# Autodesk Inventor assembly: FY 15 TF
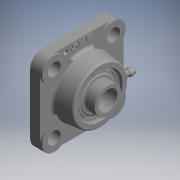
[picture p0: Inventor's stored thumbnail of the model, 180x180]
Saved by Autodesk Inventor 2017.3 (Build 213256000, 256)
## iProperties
Category: PARTsolutions
Company: SKF
Part Number: FY 15 TF
Catalog Web Link: www.cadenas.de
Description: AYF_001HC_HH_HY-Y-bearing square flanged units
Vendor: SKF
Document SubType Name: Assembly
Designer: partserver
Manufacturer: SKF
Mass: 370 g
Surface Area: 342.54 cm^2
Volume: 53.3408 cm^3
Density: 6.93652 g/cm^3
Title: FY 15 TF
Author: Cadenas PARTsolutions
Comments: Y-bearing square flanged units
PSOL_IDENT_0: {$CADENAS_DATA\23d-libs\skf\bearings_units_and_housings\bearing_units\ball_bearing_units\y-units\ayf
PSOL_IDENT_1: _001hc_hh_hy.prj},187 {VTYP=3D},{STYP=ASSTAB},{NB=FY 15 TF},{LINA=FY 15 TF},{NN=AYF_001HC_HH_HY},{DA
PSOL_IDENT_2: TE=20.08.2020 12:22:38},{GEOMDATE=20.08.2020 12:22:32},{VERSION=},{LINEID=58220},{WBVAR=COVER},{WBNU
PSOL_IDENT_3: MERIC=}  {NB=FY 15 TF},{LINA=FY 15 TF},{KT=DUMMY},{DESIGNATION=FY 15 TF},{HOUSING=FY 503 M},{BEARING=
PSOL_IDENT_4: YAR 203/15-2F},{COVER=},{DD=15},{DDX=},{DDALG=15.000},{DD1=24.200},{DD2=MIN},{DD3=},{AALG=26.000},{A=
PSOL_IDENT_5: 26},{AX=},{AXX=},{A1ALG=11.000},{A1=11},{A1X=},{A1XX=},{A3ALG=3.200},{A3=3.2},{A3X=},{A5ALG=0.000},{
PSOL_IDENT_6: A5=},{A5X=},{A5XX=},{B=27.400},{B1=MIN},{B1X=},{B4ALG=4.000},{B4=4},{B4X=},{DAAALG=55.600},{DAA=55.6
PSOL_IDENT_7: },{DAAX=},{DB=MIN},{DB1=50.000},{DB1X=},{DB2=53.000},{DB2X=},{HA=},{J=54.000},{JX=},{JXX=},{L=76.000
PSOL_IDENT_8: },{LX=},{LXX=},{N=11.500},{NX=},{NXX=},{SS1=15.900},{SS1X=},{T=32.900},{TX=},{DN=6.500},{SWN=7},{GN=
PSOL_IDENT_9: 1/4-28 SAE-LT},{RG=1/4-28 UNF},{RGX=},{R1=19},{R1X=},{J6=66},{J7=14.500},{N4=4},{D=40.000},{C=12.000
PSOL_IDENT_10: },{R12=0.300},{DW=6.747},{B3=MIN},{PITCH=28.500},{LOAD1=9.560},{LOAD2=4.750},{LOAD3=0.200},{SPEED1=9
PSOL_IDENT_11: 500},{II=1},{Z=8},{MASS=0.370},{MASSX=},{G2=M6x0.75},{HKSGS=3},{RTTGS=4},{ALPHA=},{GALG=10.000},{G=1
PSOL_IDENT_12: 0},{GX=},{GXX=},{GINALG=0.375},{GIN=0.375000002475},{GINX=},{GINXX=},{EC=},{BS=},{SLEEVE=},{POPULAR=
PSOL_IDENT_13: },{D1=MIN},{K=},{CC1=},{BRGTYP=BBY_006},{COVERALG=  '', 'No end cover' },{SUPPRESSED=unsuppressed},{
PSOL_IDENT_14: TC=FY 15 TF},{PPATH=y-bearing_square_flanged_units_parts/ayf_001hc_hh_hy_asmtpl.prj}
NB: FY 15 TF
NN: AYF_001HC_HH_HY
NT: Y-bearing square flanged units
NBSYN: $TC.
LINA: FY 15 TF
CATALOG: SKF
DESIGNATION: FY 15 TF
HOUSING: FY 503 M
BEARING: YAR 203/15-2F
COVER: No end cover
DDALG: 15
J: 54
L: 76
T: 32.9
LOAD1: 9.56
LOAD2: 4.75
SPEED1: 9500
SUPPLIER: SKF
ARTICLENO: FY 15 TF
BOMINFO: FY 15 TF
CREATOR: CADENAS GmbH
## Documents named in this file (6)
- e:\temp\worker_99\temp\exporttempdir_4692_6_LMKB5\format_0\FY 15 TF.iam
- e:\temp\worker_99\temp\exporttempdir_4692_6_LMKB5\format_0\FY 17 TF0_375000002475-dummy.ipt
- e:\temp\worker_99\temp\exporttempdir_4692_6_LMKB5\format_0\FY 503 M-housing.ipt
- e:\temp\worker_99\temp\exporttempdir_4692_6_LMKB5\format_0\1_4-28 SAE-LT.ipt
- e:\temp\worker_99\temp\exporttempdir_4692_6_LMKB5\format_0\YAR 203-2F-24_210300220312 -bearing.ipt
- e:\temp\worker_99\temp\exporttempdir_4692_6_LMKB5\format_0\17-40-27_4-12-ybrg1-43-6_747-28_5.ipt
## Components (12 placed, 5 different names)
1. FY 17 TF0_375000002475-dummy:1 — brg_XY@1 <-> housing_XY@2, brg_Z@1 <-> housing_Z@2, brg_YZ@1 <-> housing_YZ@2
2. FY 503 M-housing:1 — brg_XY@1 <-> housing_XY@2, brg_Z@1 <-> housing_Z@2, brg_YZ@1 <-> housing_YZ@2, gn_XY@2 <-> gn_XY@3, gn_Z@2 <-> gn_Z@3, gn_YZ@2 <-> gn_YZ@3, housing_XY@2 <-> brg3_XY@4, housing_Z@2 <-> brg3_Z@4, housing_YZ@2 <-> brg3_YZ@4
3. 1_4-28 SAE-LT:1 — gn_XY@2 <-> gn_XY@3, gn_Z@2 <-> gn_Z@3, gn_YZ@2 <-> gn_YZ@3
4. YAR 203-2F-24_210300220312 -bearing:1 — housing_XY@2 <-> brg3_XY@4, housing_Z@2 <-> brg3_Z@4, housing_YZ@2 <-> brg3_YZ@4, ball_1_XY@4 <-> ball_XY@5, ball_1_Z@4 <-> ball_Z@5, ball_1_YZ@4 <-> ball_YZ@5, ball_2_XY@4 <-> ball_XY@6, ball_2_Z@4 <-> ball_Z@6, ball_2_YZ@4 <-> ball_YZ@6, ball_3_XY@4 <-> ball_XY@7, ball_3_Z@4 <-> ball_Z@7, ball_3_YZ@4 <-> ball_YZ@7, ball_4_XY@4 <-> ball_XY@8, ball_4_Z@4 <-> ball_Z@8, ball_4_YZ@4 <-> ball_YZ@8, ball_5_XY@4 <-> ball_XY@9, ball_5_Z@4 <-> ball_Z@9, ball_5_YZ@4 <-> ball_YZ@9, ball_6_XY@4 <-> ball_XY@10, ball_6_Z@4 <-> ball_Z@10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
5. 17-40-27_4-12-ybrg1-43-6_747-28_5:1 — ball_1_XY@4 <-> ball_XY@5, ball_1_Z@4 <-> ball_Z@5, ball_1_YZ@4 <-> ball_YZ@5
6. 17-40-27_4-12-ybrg1-43-6_747-28_5:2 — ball_2_XY@4 <-> ball_XY@6, ball_2_Z@4 <-> ball_Z@6, ball_2_YZ@4 <-> ball_YZ@6
7. 17-40-27_4-12-ybrg1-43-6_747-28_5:3 — ball_3_XY@4 <-> ball_XY@7, ball_3_Z@4 <-> ball_Z@7, ball_3_YZ@4 <-> ball_YZ@7
8. 17-40-27_4-12-ybrg1-43-6_747-28_5:4 — ball_4_XY@4 <-> ball_XY@8, ball_4_Z@4 <-> ball_Z@8, ball_4_YZ@4 <-> ball_YZ@8
9. 17-40-27_4-12-ybrg1-43-6_747-28_5:5 — ball_5_XY@4 <-> ball_XY@9, ball_5_Z@4 <-> ball_Z@9, ball_5_YZ@4 <-> ball_YZ@9
10. 17-40-27_4-12-ybrg1-43-6_747-28_5:6 — ball_6_XY@4 <-> ball_XY@10, ball_6_Z@4 <-> ball_Z@10, ball_6_YZ@4 <-> ball_YZ@10
11. 17-40-27_4-12-ybrg1-43-6_747-28_5:7 — ball_7_XY@4 <-> ball_XY@11, ball_7_Z@4 <-> ball_Z@11, ball_7_YZ@4 <-> ball_YZ@11
12. 17-40-27_4-12-ybrg1-43-6_747-28_5:8 — ball_8_XY@4 <-> ball_XY@12, ball_8_Z@4 <-> ball_Z@12, ball_8_YZ@4 <-> ball_YZ@12
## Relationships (33: Mate 21, Angle 11, Flush 1)
- brg_XY@1 <-> housing_XY@2 [Mate]: FY 17 TF0_375000002475-dummy:1 ↔ FY 503 M-housing:1
- brg_Z@1 <-> housing_Z@2 [Mate]: FY 17 TF0_375000002475-dummy:1 ↔ FY 503 M-housing:1
- brg_YZ@1 <-> housing_YZ@2 [Angle]: FY 17 TF0_375000002475-dummy:1 ↔ FY 503 M-housing:1
- gn_XY@2 <-> gn_XY@3 [Mate]: FY 503 M-housing:1 ↔ 1_4-28 SAE-LT:1
- gn_Z@2 <-> gn_Z@3 [Mate]: FY 503 M-housing:1 ↔ 1_4-28 SAE-LT:1
- gn_YZ@2 <-> gn_YZ@3 [Angle]: FY 503 M-housing:1 ↔ 1_4-28 SAE-LT:1
- housing_XY@2 <-> brg3_XY@4 [Flush]: FY 503 M-housing:1 ↔ YAR 203-2F-24_210300220312 -bearing:1
- housing_Z@2 <-> brg3_Z@4 [Mate]: FY 503 M-housing:1 ↔ YAR 203-2F-24_210300220312 -bearing:1
- housing_YZ@2 <-> brg3_YZ@4 [Angle]: FY 503 M-housing:1 ↔ YAR 203-2F-24_210300220312 -bearing:1
- ball_1_XY@4 <-> ball_XY@5 [Mate]: YAR 203-2F-24_210300220312 -bearing:1 ↔ 17-40-27_4-12-ybrg1-43-6_747-28_5:1
- ball_1_Z@4 <-> ball_Z@5 [Mate]: YAR 203-2F-24_210300220312 -bearing:1 ↔ 17-40-27_4-12-ybrg1-43-6_747-28_5:1
- ball_1_YZ@4 <-> ball_YZ@5 [Angle]: YAR 203-2F-24_210300220312 -bearing:1 ↔ 17-40-27_4-12-ybrg1-43-6_747-28_5:1
- ball_2_XY@4 <-> ball_XY@6 [Mate]: YAR 203-2F-24_210300220312 -bearing:1 ↔ 17-40-27_4-12-ybrg1-43-6_747-28_5:2
- ball_2_Z@4 <-> ball_Z@6 [Mate]: YAR 203-2F-24_210300220312 -bearing:1 ↔ 17-40-27_4-12-ybrg1-43-6_747-28_5:2
- ball_2_YZ@4 <-> ball_YZ@6 [Angle]: YAR 203-2F-24_210300220312 -bearing:1 ↔ 17-40-27_4-12-ybrg1-43-6_747-28_5:2
- ball_3_XY@4 <-> ball_XY@7 [Mate]: YAR 203-2F-24_210300220312 -bearing:1 ↔ 17-40-27_4-12-ybrg1-43-6_747-28_5:3
- ball_3_Z@4 <-> ball_Z@7 [Mate]: YAR 203-2F-24_210300220312 -bearing:1 ↔ 17-40-27_4-12-ybrg1-43-6_747-28_5:3
- ball_3_YZ@4 <-> ball_YZ@7 [Angle]: YAR 203-2F-24_210300220312 -bearing:1 ↔ 17-40-27_4-12-ybrg1-43-6_747-28_5:3
- ball_4_XY@4 <-> ball_XY@8 [Mate]: YAR 203-2F-24_210300220312 -bearing:1 ↔ 17-40-27_4-12-ybrg1-43-6_747-28_5:4
- ball_4_Z@4 <-> ball_Z@8 [Mate]: YAR 203-2F-24_210300220312 -bearing:1 ↔ 17-40-27_4-12-ybrg1-43-6_747-28_5:4
- ball_4_YZ@4 <-> ball_YZ@8 [Angle]: YAR 203-2F-24_210300220312 -bearing:1 ↔ 17-40-27_4-12-ybrg1-43-6_747-28_5:4
- ball_5_XY@4 <-> ball_XY@9 [Mate]: YAR 203-2F-24_210300220312 -bearing:1 ↔ 17-40-27_4-12-ybrg1-43-6_747-28_5:5
- ball_5_Z@4 <-> ball_Z@9 [Mate]: YAR 203-2F-24_210300220312 -bearing:1 ↔ 17-40-27_4-12-ybrg1-43-6_747-28_5:5
- ball_5_YZ@4 <-> ball_YZ@9 [Angle]: YAR 203-2F-24_210300220312 -bearing:1 ↔ 17-40-27_4-12-ybrg1-43-6_747-28_5:5
- ball_6_XY@4 <-> ball_XY@10 [Mate]: YAR 203-2F-24_210300220312 -bearing:1 ↔ 17-40-27_4-12-ybrg1-43-6_747-28_5:6
- ball_6_Z@4 <-> ball_Z@10 [Mate]: YAR 203-2F-24_210300220312 -bearing:1 ↔ 17-40-27_4-12-ybrg1-43-6_747-28_5:6
- ball_6_YZ@4 <-> ball_YZ@10 [Angle]: YAR 203-2F-24_210300220312 -bearing:1 ↔ 17-40-27_4-12-ybrg1-43-6_747-28_5:6
- ball_7_XY@4 <-> ball_XY@11 [Mate]: YAR 203-2F-24_210300220312 -bearing:1 ↔ 17-40-27_4-12-ybrg1-43-6_747-28_5:7
- ball_7_Z@4 <-> ball_Z@11 [Mate]: YAR 203-2F-24_210300220312 -bearing:1 ↔ 17-40-27_4-12-ybrg1-43-6_747-28_5:7
- ball_7_YZ@4 <-> ball_YZ@11 [Angle]: YAR 203-2F-24_210300220312 -bearing:1 ↔ 17-40-27_4-12-ybrg1-43-6_747-28_5:7
- ball_8_XY@4 <-> ball_XY@12 [Mate]: YAR 203-2F-24_210300220312 -bearing:1 ↔ 17-40-27_4-12-ybrg1-43-6_747-28_5:8
- ball_8_Z@4 <-> ball_Z@12 [Mate]: YAR 203-2F-24_210300220312 -bearing:1 ↔ 17-40-27_4-12-ybrg1-43-6_747-28_5:8
- ball_8_YZ@4 <-> ball_YZ@12 [Angle]: YAR 203-2F-24_210300220312 -bearing:1 ↔ 17-40-27_4-12-ybrg1-43-6_747-28_5:8
